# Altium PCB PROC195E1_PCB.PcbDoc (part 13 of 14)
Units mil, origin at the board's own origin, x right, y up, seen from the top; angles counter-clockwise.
Board outline 3110.24 x 2500 mil, 10 copper layers (Top Layer, L02_GND1, L03_SIG1, L04_GND2, L05_PWR1, L06_PWR2, L07_GND3, L08_SIG2, L09_GND4, Bottom Layer), stack 66.407 mil thick; 571 components, 538 nets, 6726 pads, 1286 vias.
Unrouted connection lines stored in the file: 4.
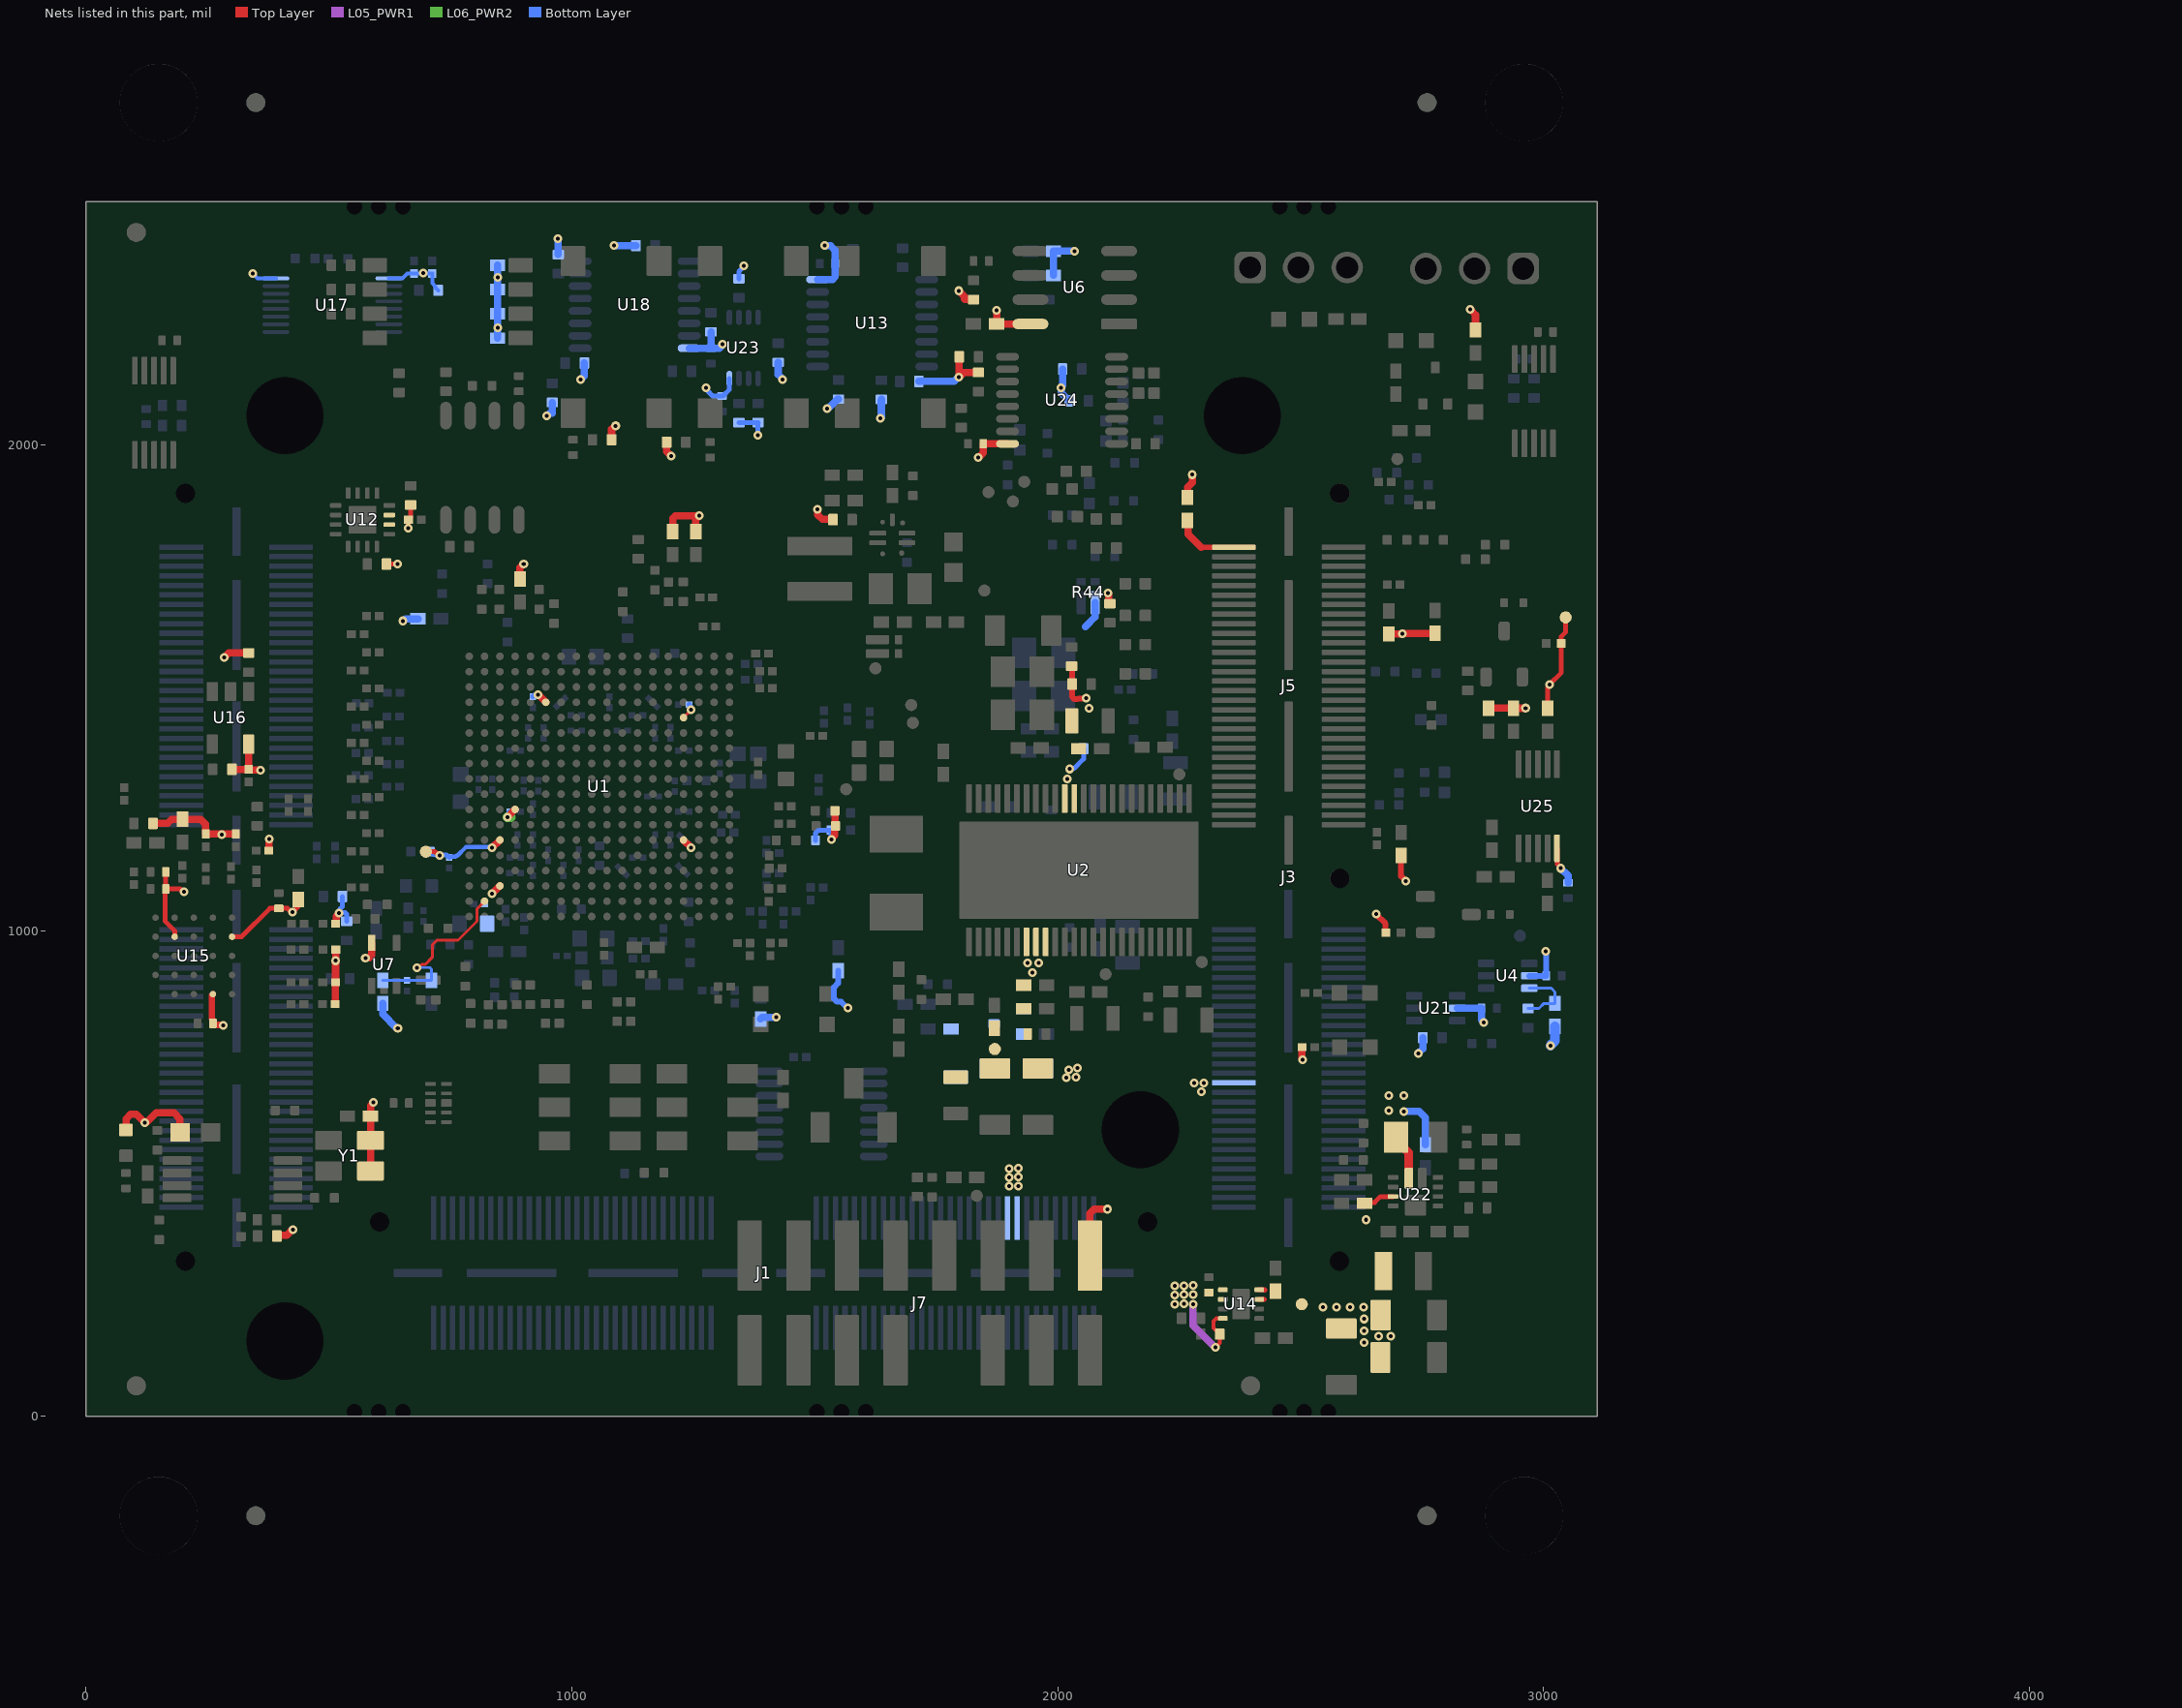
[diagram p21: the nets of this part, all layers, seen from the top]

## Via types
v1: diameter 18, hole 8, Top Layer to Bottom Layer, tented both sides, 1226 vias
v2: diameter 19.68, hole 7.87, Top Layer to Bottom Layer, tented top, 54 vias
v3: diameter 19.68, hole 7.87, Top Layer to Bottom Layer, 4 vias
v4: diameter 19.68, hole 7.87, Top Layer to Bottom Layer, tented both sides, 2 vias

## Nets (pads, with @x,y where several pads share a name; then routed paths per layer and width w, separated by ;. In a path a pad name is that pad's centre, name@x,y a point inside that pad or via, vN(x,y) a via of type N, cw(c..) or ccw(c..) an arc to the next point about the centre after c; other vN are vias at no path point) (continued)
VDDS18_LDO_1V8: C40.1 C44.1 C45.1 C46.1 C47.1 C48.1 U1.D6 U1.E15 U1.L4 U1.N15 U1.T3 U7.5 | length 210.6
  Top Layer w5.8: U1.E15@1230.11,1438.42 v1(1245.86,1454.17)
  Top Layer w15: v1(575.42,943.31) 575.99,943.89 583.25,943.89 588.39,949.02 U7.5@588.39,974.72 ; v1(836.41,1076.22) U1.T3@852.16,1091.97 ; v1(867.91,1233.7) U1.L4@883.65,1249.45 ; v1(930.9,1485.67) U1.D6@946.64,1469.92 ; U1.N15@1230.11,1186.45 v1(1245.86,1170.71)
  L06_PWR2 w20: v1(867.91,1233.7) 874.3,1233.7 v1@874.4,1233.8
  Bottom Layer w10: v1(867.91,1233.7) 867.91,1235.86 870.82,1238.78 870.82,1243.4 872.12,1244.7 C45.1@872.91,1244.7 ; C47.1@919.9,1481.22 919.9,1482 921.2,1483.3 921.98,1483.3 922.81,1484.14 929.37,1484.14 v1(930.9,1485.67) ; C44.1@1238.54,1179.19 1238.54,1178.61 1245.86,1171.29 v1(1245.86,1170.71) ; C48.1@1241.41,1465.17 1242.2,1465.17 1243.49,1463.87 1243.49,1463.08 1244.33,1462.25 1244.33,1455.7 v1(1245.86,1454.17)
VMAIN_5V0: C62.1 C80.1 C84.1 C85.1 C92.1 L3.1 R12.2 R58.1 R249.1 TP3.1 U14.7 U14.8 U22.9 | length 222
  Top Layer w10: U14.7@2414.76,241.02 2414.84,241.1 2425.74,241.1 ; U14.8@2414.76,260.71 2414.84,260.63 2426.27,260.63 2426.78,260.12 ; C92.1@2631.61,438.59 2633.6,440.57 2652.26,440.57 2664.3,452.61 U22.9@2690.19,452.61
  Top Layer w15: R58.1@2502.85,759.91 2502.85,736.24 2503.95,735.14 v1(2503.95,734.33)
  Bottom Layer w15: R12.2@611.15,850.21 611.28,850.09 611.28,828.11 639.63,799.76 641.58,799.76 v1(642.15,799.19)
  Bottom Layer w20: v1(3013.92,763.44) 3023.19,772.71 R249.1@3023.19,802.88
  other v1: 2630.86,151.86 2660.17,165.33 2685.15,165.35 2630.39,176.22 2630.27,200.57 2546.33,224.67 2574.01,224.67 2601.69,224.67 2629.37,224.67 2634.75,404.82
VMAIN_5V0_IN: C79.1 J1.18 J1.20 J3.27 R82.2 U14.1 U14.2 U14.4 | length 194
  Top Layer w8: v1(2324.25,141.98) 2333.58,151.31 R82.2@2333.58,169.51 2333.58,171.48 2327.74,177.32 2325.77,177.32 2321.02,182.08 2321.02,196 2326.91,201.89 2339.71,201.89 U14.4@2339.96,201.65
  L05_PWR1 w15: v1(2278.69,231.34) 2278.69,187.54 v1(2324.25,141.98)
  other v1: 2241.37,231.39 2260.04,231.77 2241.37,250.27 2260.04,250.46 2278.69,250.45 2241.37,269.15 2260.04,269.15 2278.69,269.55 1900.21,474.19 1919.42,474.49 1900.61,492.15 1918.97,493.16 1900.61,510.31 1918.77,510.91 2296.23,668.16 2280.72,686.14 2300.95,686.14
VMAIN_12V0: C58.1 C59.2 C60.2 C63.1 C64.1 C65.2 C66.2 C67.1 C68.1 C69.1 C94.1 C100.2 C167.1 C168.1 R16.2 R190.2 TP6.1 U2.7 U2.8 U2.9 U22.6 | length 201.5
  Top Layer w18: C100.2@2696.77,574.77 2696.77,568.27 2722.67,542.37 U22.6@2722.67,490.01
  Bottom Layer w15: v1(2712.11,627.97) 2743.98,627.97 2756.8,615.14 R190.2@2756.8,559.14
  other v1: 2681.85,629.37 2681.85,660.61 2712.11,660.61 2018.15,696.97 2037.81,698.38 2023.07,713.47 2040.62,717.33 1947.78,913.5 1938.54,933.46 1960.71,933.66
VMAIN_MON: R249.2 R251.1 U4.6 | length 139
  Bottom Layer w5.8: R251.1@2968,839.54 2990.11,839.54 3000.7,850.12 R249.2@3023.19,850.12 3023.19,873.79 3015.61,881.37 U4.6@2970.56,881.37
VPP_1V8: C23.1 R10.1 TP1.1 U1.N3 | length 203.3
  Top Layer w10: TP1.1@699.97,1162.37 700.03,1162.31 718.8,1162.31 720.46,1160.65 726.89,1154.23 v1(728.66,1154.23)
  Top Layer w15: v1(836.41,1170.71) U1.N3@852.16,1186.45
  Bottom Layer w9: R10.1@709.32,1162.37 709.32,1161.88 714.17,1157.03 714.66,1157.03 715.75,1155.95 v1@720.46,1155.95 ; C23.1@749.48,1152.31 760.79,1152.31 762.87,1154.38 765.04,1154.38 782.32,1171.67 v1@837.37,1171.67
  Bottom Layer w10: v1(728.66,1154.23) 727.13,1155.76 720.65,1155.76 720.46,1155.95 742.68,1155.95 745.81,1152.82 746.6,1152.82 747.89,1151.52 C23.1@747.89,1150.73
VREF_DEBUG: J5.1 R59.1 | length 133.7
  Top Layer w11: 2294.85,1789.15 J5.1@2362.59,1789.15
  Top Layer w15: R59.1@2267.59,1843.82 2268.06,1843.35 2268.06,1815.94 2294.85,1789.15
VSYS_3V3_LDO1: C56.1 C75.2 C76.1 C77.1 C78.1 C95.1 C104.1 C105.1 C129.1 C130.2 C131.1 C137.1 C138.1 C139.1 C140.1 C141.1 C156.1 C157.1 C160.1 C161.1 C174.1 FB3.1 J7.1 R19.1 R20.1 R21.1 R22.1 R37.2 R40.2 R41.1 R44.3 R46.2 R47.2 R48.2 R49.2 R50.2 R59.2 R68.1 R80.2 R81.2 R104.2 R105.2 R157.2 R158.2 R175.2 R176.2 R177.2 R178.2 R179.2 R180.2 R181.2 R182.2 R183.2 R184.1 R185.2 R202.2 R203.2 R205.2 R206.2 R216.1 R218.2 R219.2 R220.2 R221.2 R222.2 R233.2 R234.2 R245.1 R246.1 R248.1 R250.1 R252.1 R253.1 R254.1 R255.1 R256.1 R257.1 R260.2 R266.2 R267.2 R268.2 R279.2 R280.2 R298.1 R299.1 R300.1 R301.1 R304.1 R305.1 R306.1 R307.1 R308.1 TP10.1 U2.37 U2.38 U4.5 U6.8 U12.14 U12.15 U13.16 U15.B4 U15.D1 U15.E4 U16.5 U17.1 U17.16 U18.16 U21.5 U23.8 U24.16 U25.10 Y1.1 Y1.4 | length 4831.7
  Top Layer w10: C137.1@164.77,1120.78 C140.1@164.77,1085.78 ; U15.B4@182.96,987.35 182.89,987.42 182.89,999.65 163.81,1018.73 163.81,1084.82 C140.1@164.77,1085.78 ; v1(201.76,1079.47) 200.41,1079.47 194.1,1085.78 C140.1@164.77,1085.78 ; U15.E4@301.07,987.35 320.57,987.35 378.93,1045.71 415.33,1045.71 421.28,1039.76 421.96,1039.76 423.49,1038.23 v1(425.65,1038.23) 437.26,1049.83 C75.2@437.28,1064.05 ; R80.2@618.86,1754.31 619,1754.45 641.5,1754.45 v1(641.64,1754.59) ; v1(663.86,1828.23) 663.99,1828.36 663.99,1845.36 C131.1@664.12,1845.49 ; C131.1@664.9,1845.49 668.17,1848.76 668.17,1854.16 668.63,1854.62 R81.2@668.63,1876.03 ; R268.2@3008.15,1457.6 3008.15,1500.45 3012.01,1504.31 v1(3012.01,1506.48) 3036.51,1530.98 R280.2@3036.51,1591.21 3036.51,1605.47 3045.37,1614.33 TP10.1@3045.37,1644.52 ; U25.10@3027.57,1169.45 3028.48,1168.54 3028.48,1136.82 3034.86,1130.44 v1(3034.86,1128.28)
  Top Layer w12: R22.1@2028.96,1544.31 2029.4,1543.86 2029.4,1507.71 R21.1@2029.84,1507.27 2029.84,1481.07 2034.53,1476.38 2041.16,1476.38 2042.38,1477.6 2057.68,1477.6 v1(2058.82,1478.75) ; v1(2655.2,1033.91) 2674.77,1014.34 2674.77,996.11 R279.2@2675.24,995.64 ; R260.2@2706.82,1154.94 2706.82,1111.99 2716.57,1102.24 v1(2716.57,1101.82)
  Top Layer w13: C139.1@261.7,807.27 263.07,805.9 280,805.9 281.22,804.67 v1(282.57,804.67) ; C139.1@261.7,809.24 260.33,810.61 260.33,817.98 259.88,818.42 259.88,867.32 261.7,869.13 U15.D1@261.7,869.24
  Top Layer w15: FB3.1@82.8,589.68 82.8,612.3 92.28,621.78 104.39,621.78 v1(121.78,604.39) 122.59,604.39 124.09,605.89 125.89,605.89 144.66,624.66 181.83,624.66 194.19,612.3 C129.1@194.19,584.5 ; R183.2@138.5,1220.75 168.35,1220.75 176.88,1229.28 R180.2@199,1229.28 236.4,1229.28 246.98,1218.69 R179.2@246.98,1198.97 277.92,1198.97 279.31,1197.58 v1(280.12,1197.58) 280.93,1197.58 282.32,1198.97 R178.2@308.96,1198.97 ; v1(282.57,804.67) v1@283.15,804.1 ; v1(284.5,1562.09) 285.31,1562.09 294.52,1571.31 R205.2@335.2,1571.31 ; R206.2@300.75,1332.07 300.87,1331.95 335.08,1331.95 C141.1@335.2,1331.83 ; U16.5@335.2,1383.67 335.2,1331.19 335.96,1330.42 359.25,1330.42 v1(359.82,1329.85) ; R182.2@376.93,1164.69 377.55,1165.31 377.55,1188.42 v1(377.85,1188.72) ; R46.2@393.24,371.39 395.06,373.21 413.73,373.21 425.15,384.62 v1(425.96,384.62) ; R175.2@513.37,848.86 513.57,849.06 513.57,893.56 514.12,894.1 514.12,937.61 v1(514.46,937.95) ; v1@514.27,938.27 514.27,960.08 R176.2@514.41,960.22 ; R177.2@515.15,1014.32 515.57,1014.73 515.57,1029.72 521.4,1035.56 v1(521.4,1036.37) ; Y1.4@585.95,505.16 Y1.1@585.95,568.15 585.95,640.1 591.6,645.76 v1(591.6,646.57) ; R157.2@893.69,1723.67 893.69,1746.82 901.23,1754.36 v1(901.23,1754.65) ; R245.1@1082.1,2010.26 1082.1,2032.06 1088.48,2038.44 1089.98,2038.44 v1(1090.55,2039.01) ; R250.1@1195.53,2005.26 1195.53,1986.67 1205.02,1977.18 v1(1205.02,1977.12) ; R202.2@1207.93,1821.07 1207.93,1848.24 1213.49,1853.8 v1@1262.1,1853.8 ; R203.2@1255.29,1821.07 1255.29,1846.18 v1(1262.91,1853.8) ; v1(1505.31,1867.23) 1505.89,1866.66 1505.89,1856.03 1515.6,1846.32 R37.2@1537.68,1846.32 ; v1(1534.08,1187.61) 1534.08,1188.42 1541.32,1195.65 1541.32,1213.44 R104.2@1543.17,1215.29 ; R104.2@1541.81,1216.16 R105.2@1541.81,1246.63 ; v1(1796.85,2139.23) 1797.22,2139.61 1797.22,2180.75 R256.1@1797.52,2181.04 ; v1(1796.85,2317.03) 1796.85,2316.22 1807.58,2305.49 1807.58,2300.4 1809.09,2298.88 R252.1@1826.89,2298.88 ; v1@1798.23,2139.81 1807.31,2148.89 R257.1@1836.89,2148.89 ; v1(1836.26,1973.36) 1837.07,1973.36 1846.89,1983.17 C160.1@1846.89,2002.06 U24.16@1896.89,2002.06 ; v1(1874.74,2276.26) 1874.38,2275.89 1874.38,2248.98 C77.1@1874.01,2248.61 U6.8@1944.01,2248.61 ; J7.1@2066.47,331.06 2066.47,417.94 2075.26,426.73 v1(2102.75,426.73) ; v1(2103.36,1694.92) 2104.89,1693.39 2104.89,1675.65 R19.1@2107.45,1673.09 ; R59.2@2267.07,1891.58 2267.07,1912.79 2277.1,1922.81 v1@2277.1,1938.36 ; R216.1@2681.28,1610.44 2681.51,1610.67 2709.15,1610.67 2709.81,1611.32 2776.22,1611.32 R40.2@2776.65,1611.76 ; v1(2849.24,2278.26) 2859.8,2267.7 R68.1@2859.8,2236.18 ; R266.2@2886.74,1457.68 2886.79,1457.64 R267.2@2938.15,1457.6 R267.2@2938.15,1457.6 2962.48,1457.6 v1(2962.96,1458.07)
  Bottom Layer w8: v1(343.26,2352.54) 353.38,2342.42 U17.16@391.42,2342.42 ; U17.1@623.7,2342.42 651.26,2342.42 661.29,2352.45 C78.1@675.4,2352.45 675.8,2352.84 693.88,2352.84 v1(694.28,2353.24) 694.67,2352.84 712.67,2352.84 C76.1@713.06,2352.45 713.06,2332.07 719.25,2325.88 719.25,2323.79 R222.2@725.09,2317.95
  Bottom Layer w10: R185.2@528.27,1070.27 528.27,1049.46 523.18,1044.38 523.18,1043.81 522.93,1043.56 522.93,1037.9 v1(521.4,1036.37) 522.24,1037.21 533.66,1037.21 537.17,1033.69 R184.1@537.17,1019.27 ; v1(1275.99,2116.87) 1275.99,2114.71 1284.52,2106.18 1284.52,2106.08 1290.38,2100.22 C161.1@1309.22,2100.22 1311.19,2100.22 1324.48,2113.51 U23.8@1324.48,2136.43 ; R248.1@1344.16,2045.58 R41.1@1383.53,2045.58 1383.45,2045.49 1383.45,2019.29 v1(1383.36,2019.2) ; R253.1@1344.16,2341.78 1344.16,2356.82 1354.31,2366.97 v1(1354.31,2368.34) ; R234.2@1501.58,1185.59 1501.65,1185.65 1501.65,1200.33 1508.21,1206.89 R233.2@1533.7,1206.89 1533.89,1206.7 1533.89,1187.8 v1(1534.08,1187.61) ; v1(2024.59,1332.56) 2026.12,1334.09 2034.02,1334.09 2053.4,1353.47 R20.1@2053.4,1374.47
  Bottom Layer w12: R47.2@1548.35,917.56 1548.35,892.1 1539.61,883.36 1539.61,859.91 1546.03,853.49 1554.51,853.49 1567.61,840.4 v1(1568.29,840.4) ; U4.5@2970.56,906.96 C157.1@3005.56,906.96 3005.56,956.13 v1(3004.47,957.23)
  Bottom Layer w15: v1(652.78,1637.44) 653.59,1637.44 657.95,1641.8 R158.2@683.73,1641.8 ; R221.2@847.63,2219.54 v1(847.63,2241.19) R220.2@847.63,2269.54 R219.2@847.63,2319.54 v1(847.63,2344.54) R218.2@847.63,2369.54 ; v1(948.91,2059.78) 949.72,2059.78 954.72,2064.77 960.1,2064.77 R304.1@960.1,2087.12 ; v1(971.19,2423.85) 971.19,2423.04 972.3,2421.93 R306.1@972.3,2391.57 ; v1(1018.04,2133.93) 1026.01,2141.9 R305.1@1026.01,2168.12 ; v1(1087.54,2409.8) R307.1@1132.13,2409.8 ; U18.16@1241.71,2198.65 C56.1@1286.71,2198.65 ; R308.1@1286.71,2232.34 C56.1@1286.71,2198.65 ; v1(1310.32,2206.78) 1310.32,2205.96 1308.06,2203.7 1308.06,2202.83 1303.88,2198.65 1289.06,2198.65 C56.1@1286.71,2198.65 ; R48.2@1388.78,818.12 1391.95,821.29 1419.96,821.29 v1(1420.53,821.86) ; R301.1@1424.91,2169.57 1424.91,2144.25 1434.13,2135.03 v1(1434.13,2134.22) ; U13.16@1506.16,2340.02 1536.55,2340.02 1542.11,2345.59 1542.11,2399.9 1532.51,2409.5 1521.59,2409.5 v1(1521.01,2410.07) ; v1(1525.47,2074.06) 1526.05,2074.63 1527.67,2074.63 1546.92,2093.88 R300.1@1548.89,2093.88 ; v1(1635.04,2054.25) 1635.04,2055.06 1637.14,2057.17 1637.14,2091.01 1637.24,2091.1 R298.1@1637.24,2093.35 ; R299.1@1714.44,2130.44 1787.32,2130.44 1796.12,2139.23 v1(1796.85,2139.23) ; R49.2@1991.25,2348.61 R50.2@1991.25,2398.61 v1(2035.19,2398.61) ; R255.1@2010.22,2155.79 2010.22,2151.56 2010.13,2151.48 2010.13,2121.4 2006.92,2118.19 v1(2006.92,2117.38) 2007.5,2116.8 2007.5,2106.72 R254.1@2023.86,2090.36 ; 2056.94,1625.9 2076.99,1645.94 2076.99,1674.86 R44.3@2077.07,1674.95 ; v1(2741.86,746.66) 2741.86,747.47 2751.44,757.05 R246.1@2751.44,779.4 ; U21.5@2822.2,840.27 C156.1@2872.2,840.27 2872.2,816.42 2877.12,811.5 v1(2877.12,810.69) ; v1(3034.86,1128.28) 3050.22,1112.91 C174.1@3050.22,1098.29
  other v1: 2019.68,1311.78 2064.77,1457.57 2709.38,1610.89 2277.15,1938.41
VSYS_MON_AM26x: C57.1 R12.1 R13.2 U1.U2 | length 380.3
  Top Layer w5.66: 804.91,1018.93 804.91,1044.72
  Top Layer w5.8: v1(681.68,923.27) 683.75,923.27 691.18,930.69 698.81,930.69 713.11,944.99 713.11,970.58 722.68,980.15 766.14,980.15 773.33,987.34 778.16,992.17 804.91,1018.93 ; 804.91,1044.72 U1.U2@820.66,1060.47
  Bottom Layer w5.8: R12.1@611.15,897.46 C57.1@661.15,897.46 R13.2@711.15,897.46 711.15,920.66 707.75,924.06 682.47,924.06 v1(681.68,923.27)
pads on no net: Designator7. Designator7_1. Designator8. Designator8_1. Designator9. Designator9_1. FID1.1 FID2.1 FID3.1 FID4.1 FID5.1 FID6.1 FID7.1 FID8.1 FID9.1 FID10.1 FID12.1 FID13.1 FID14.1 FID15.1 J1.27 J1.40 J1.42 J1.44 J1.46 J1.47 J1.62 J1.64 J1.66 J1.68 J1.76 J1.79 J1.80 J1.81 J1.82 J1.84 J1.86 J1.88 J1.MH1 J1.MH2 J2.12 J2.24 J2.27 J2.29 J2.31 J2.33 J2.35 J2.37 J2.39 J2.41 J2.42 J2.43 J2.44 J2.45 J2.47 J2.49 J2.51 J2.61 J2.62 J2.63 J2.64 J2.65 J2.66 J2.67 J2.68 J2.69 J2.70 J2.71 J2.72 J2.73 J2.74 J2.75 J2.76 J2.77 J2.78 J2.79 J2.80 J2.81 J2.82 J2.83 J2.84 J2.85 J2.86 J2.87 J2.88 J2.89 J2.90 J2.91 J2.92 J2.93 J2.94 J2.95 J2.96 J2.97 J2.98 J2.99 J2.100 J2.101 J2.102 J2.103 J2.104 J2.105 J2.106 J2.107 J2.108 J2.109 J2.111 J2.MH1 J2.MH2 J3.1 J3.2 J3.3 J3.4 J3.5 J3.6 J3.7 J3.8 J3.9 J3.10 J3.11 J3.12 J3.13 J3.14 J3.15 J3.16 J3.17 J3.18 J3.19 J3.20 J3.21 J3.22 J3.23 J3.24 J3.25 J3.26 J3.28 J3.30 J3.32 J3.34 J3.36 J3.38 J3.39 J3.40 J3.41 J3.42 J3.43 J3.44 J3.45 J3.46 J3.47 J3.48 J3.49 J3.50 J3.51 J3.52 J3.53 J3.55 J3.58 J3.60 J3.61 J3.62 J3.63 J3.64 J3.65 J3.67 J3.69 J3.71 J3.73 J3.74 J3.75 J3.77 J3.79 J3.81 J3.86 J3.98 J3.103 J3.107 J3.110 J3.MH1 J3.MH2 J5. J5.8 J5.9 J5.10 J5.11 J5.14 J5.18 J5.20 J5.22 J5.24 J5.26 J5.28 J5.30 J5.32 J5.34 J5.36 J5.38 J5.40 J5.42 J5.44 J5.46 J5.48 J5.50 J5.51 J5.52 J5.53 J5.54 J5.55 J5.56 J5.59 J5.60 J8.2 J9.2 MH1.1 MH2.1 MH3.1 MH4.1 U7.1 U9.3 U10.3 U11.8 U11.9 U11.10 U12.17@569.55,1845.49 U13.13 U15.A2 U15.A3 U15.B1 U15.B5 U15.C5 U20.3@742.01,645.23 U20.4 U20.6 U20.7 U20.8@709.14,645.23 U22.0

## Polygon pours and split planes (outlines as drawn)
VSYS_3V3_LDO1 on L05_PWR1 "NONET_L08_P-001" (solid, remove dead copper, pour order 109): 0,2500 0,0 3110.24,0 3110.24,2500
VDDA_3V3 on L05_PWR1 "NONET_L08_P-001" (solid, remove dead copper, pour order 88): 1184.22,979.48 1190.02,973.68 1190.02,788.7 1284.52,694.2 1469.5,694.2 1499.57,664.12 1499.57,622.1 1466.37,588.9 795.53,588.9 780.23,573.6 678.67,573.6 651,601.28 651,661.55 688.63,699.18 740.93,699.18 756.64,714.9 816.6,714.9 910.85,714.9 1056.88,860.93 1055,972.34 1062.14,979.48
VMAIN_12V0 on L05_PWR1 "NONET_L08_P-001" (solid, remove dead copper, pour order 89): 2757.6,684.51 2679.96,762.15 2679.96,982.8 2670.51,992.24 1958.84,992.24 1920.28,953.69 1920.28,695.73 1955.8,660.21 2039.77,660.21 2113.24,733.68 2113.24,736.1 2356.99,736.1 2487.1,605.99 2728.79,605.99 2736.77,614.77 2757.6,635.6
VCC_1V2 on L05_PWR1 "NONET_L08_P-001" (solid, remove dead copper, pour order 86): 890.66,1155.07 898.11,1147.63 1093.07,1147.63 1120.5,1120.2 1437.73,1120.2 1610.67,1293.14 1610.67,1578.88 1597.25,1592.29 1413.83,1592.29 1321.85,1684.28 794.18,1684.28 706.44,1596.55 706.44,1267.24 878.82,1267.24 890.66,1255.39
DAC_VREF on L05_PWR1 "NONET_L-01_P-001" (solid, remove dead copper, pour order 80): 1181.69,1093.43 1559.34,1093.43 1575.41,1077.36 1575.41,1000.43 1556.98,982 1210.37,982 1170.37,1022 1170,1022 1170,1081.74
VDDA18_OSC_PLL_AM26x on L05_PWR1 "NONET_L08_P-001" (solid, remove dead copper, pour order 92): 867.9,1183.71 688.67,1183.71 678.22,1173.26 678.22,1078.76 687.4,1069.59 865.31,1069.59 881.56,1085.84 881.56,1171.32 874.38,1178.51
VDDA18_LDO_1V8 on L05_PWR1 "NONET_L08_P-001" (solid, remove dead copper, pour order 81): 999.93,1119.73 991.47,1128.19 913.6,1128.19 913.6,1069.29 1000.39,1069.29 1006.19,1075.09 1006.19,1115.18
GND on Bottom Layer "GND_L10_P103" (solid, remove dead copper, pour order 103): 0,2500 3110.24,2500 3110.24,0 0,0
VDD_IO_3V3 on Bottom Layer "NONET_L08_P-001" (solid, remove dead copper, pour order 0): 2044.88,1698.21 2034.02,1709.07 2023.26,1709.07 2019.05,1704.87 2019.05,1651.45 2026.34,1644.16 2036,1644.16 2042.81,1650.97 2060.59,1650.97 2061.74,1652.12 2061.74,1697.04 2060.57,1698.21
GND on Bottom Layer "NONET_L08_P-001" (solid, remove dead copper, pour order 52): 2036.46,1603.56 2019.08,1620.95 2019.08,1719.76 2017.11,1721.34 1947.41,1721.34 1947.41,1670.79 1971.46,1646.74 1971.46,1356.07 2012.8,1356.07 2016.84,1360.11 2016.84,1424.44 2036.46,1443.49
VMAIN_12V0 on Bottom Layer "NONET_L08_P-001" (solid, remove dead copper, pour order 33): 1926.45,935.67 1926.45,931.21 1899.58,904.16 1899.58,830.11 1888.81,819.34 1771.78,819.34 1757.31,804.87 1757.31,679.88 1766.14,671.05 2055.32,671.05 2070.48,686.21 2070.48,740.07 2055.42,755.13 1958.19,755.13 1945.42,767.91 1945.42,886.13 1965.1,905.82 1965.1,924.32 1965.1,939.77 1962.05,942.82 1933.6,942.82
VDD_IO_3V3 on Bottom Layer "NONET_L08_P-001" (solid, remove dead copper, pour order 7): 1550.42,1403.93 1550.42,1300.28 1603.34,1300.28 1612.9,1309.85 1612.9,1394.36 1603.34,1403.93
VCC_1V2 on Bottom Layer "NONET_L08_P-001" (solid, remove dead copper, pour order 38): 753.84,1305.09 748.91,1310.02 735.27,1310.02 725.48,1319.81 725.48,1339.58 731.85,1345.95 840.43,1345.95 847.94,1338.44 847.94,1330.93 862.96,1315.92 884.18,1294.69 937.14,1294.69 942.89,1288.94 942.89,1258.57 937.97,1253.66 913.6,1253.66 910.86,1256.4 892.27,1256.4 885.18,1263.49 885.18,1271.81 873.78,1283.2 851.89,1305.09 834.83,1305.09
VCC_1V2 on Bottom Layer "NONET_L08_P-001" (solid, remove dead copper, pour order 1): 1080.76,1655.54 1091.87,1644.43 1091.87,1613.46 1072.51,1594.11 1072.51,1514.34 1082.82,1504.04 1098.52,1504.04 1105.55,1497.01 1105.55,1478.36 1097.38,1470.19 1071.19,1470.19 1064.04,1463.04 1064.04,1417.86 1051.55,1405.38 1013.3,1405.38 1013.3,1462.84 1018.22,1467.76 1032.71,1467.76 1039.28,1474.32 1039.28,1528.29 1032.79,1534.78 1032.79,1646.41 1041.92,1655.54
VCC_6V0 on Bottom Layer "NONET_L08_P-001" (solid, remove dead copper, pour order 48): 1837.54,1514.63 1820,1532.17 1820,1643 1837.54,1660 1837.54,1749.84 1796.26,1791.13 1796.26,1817.53 1831.75,1853.02 1855.95,1853.02 1905.97,1803.01 1920.94,1788.03 1920.94,1655.42 1955.71,1620.65 1955.71,1615.57 1955.71,1346.14 1961.51,1340.34 1961.51,1304.13 1900.35,1304.13 1900.35,1351.67 1896.06,1355.96 1853.71,1355.96 1837.54,1372.13
VDDA_3V3 on Bottom Layer "NONET_L08_P-001" (solid, remove dead copper, pour order 62): 1062.67,1008.75 1089.49,1008.75 1090.64,1007.6 1090.64,993.63 1105.23,979.05 1105.23,935.37 1061.4,935.37 1060.28,936.49 1060.28,1007.16 1061.29,1008.18
GND on Bottom Layer "NONET_L08_P-001" (solid, remove dead copper, pour order 5): 1428.35,1396.14 1431.6,1392.9 1431.6,1353.33 1427.6,1349.33 1330.2,1349.33 1318.92,1338.05 1298.66,1338.05 1294.85,1341.87 1294.85,1368.72 1300.71,1374.59 1316.19,1374.59 1337.75,1396.14
VSYS_3V3_LDO1 on Bottom Layer "NONET_L08_P-001" (solid, remove dead copper, pour order 61): 2089.17,1700.86 2093.02,1704.71 2113.37,1704.71 2114.43,1703.64 2114.43,1691.45 2114.43,1649.35 2079.79,1614.71 2079.79,1484.04 2079.79,1446.04 2079.79,1401.21 2064.92,1386.34 2064.92,1353.86 2037.05,1325.99 2037.05,1310.81 2024.98,1298.74 2012.92,1298.74 2006.82,1304.84 2006.82,1328.71 2032.24,1354.13 2032.24,1416.55 2051.91,1436.21 2051.91,1635.51 2068.3,1651.9 2067.68,1652.52 2067.68,1695.21 2073.33,1700.86
GND on Bottom Layer "NONET_L08_P-001" (solid, remove dead copper, pour order 39): 752.46,1277.05 720.73,1277.05 720.73,1230.85 722.19,1229.39 815.05,1229.39 821.95,1236.29 821.95,1269.8 835.19,1283.04 842.95,1283.04 842.95,1297.22 772.63,1297.22
VMAIN_5V0_IN on Bottom Layer "NONET_L08_P-001" (solid, remove dead copper, pour order 16): 1891.57,363.19 1891.57,464.1 1886.98,468.68 1886.98,512.62 1893.54,519.18 1923.12,519.18 1927.85,514.45 1927.85,469.41 1922.25,463.82 1922.25,363.19
GND on Bottom Layer "NONET_L08_P-001" (solid, remove dead copper, pour order 37): 1992.29,577.16 1774.34,577.16 1764.06,586.88 1764.06,643.03 1988.79,643.03 1992.29,639.54
VCC_1V2 on Bottom Layer "NONET_L08_P-001" (solid, remove dead copper, pour order 3): 1436.03,1283.01 1436.03,1334.12 1289.89,1334.12 1286.01,1338 1267.18,1338 1263.9,1334.72 1263.9,1311.71 1249.26,1297.07 1176.34,1297.07 1168.87,1289.6 1168.87,1263 1175.15,1256.73 1222.66,1256.73 1244.97,1279.04 1432.06,1279.04
GND on Bottom Layer "NONET_L08_P-001" (solid, remove dead copper, pour order 64): 949.57,933.53 945.04,933.53 941.63,936.74 941.63,992.44 947.55,992.44 963.85,1008.75 1032.81,1008.75 1033.38,1008.18 1033.38,1007.37 1033.95,1006.8 1033.95,978.01 987.5,978.01 975.88,966.38 975.88,941.48 957.52,941.48
3V3_LDO2 on Bottom Layer "3V3_LDO2_L10_P096" (solid, pour order 96): 1834.58,560.18 1841.61,553.16 1841.61,517.8 1827.37,503.57 1827.37,456.73 1823.83,453.19 1823.83,363.19 1812.83,363.19 1812.83,453.19 1808.4,457.62 1808.4,555.07 1813.51,560.18
GND on Bottom Layer "NONET_L08_P-001" (solid, remove dead copper, pour order 8): 1688.66,1394.74 1688.66,1311.34 1677.6,1300.28 1635.74,1300.28 1626.18,1309.85 1626.18,1394.36 1635.74,1403.93 1679.59,1403.93
GND on Bottom Layer "NONET_L08_P-001" (solid, remove dead copper, pour order 2): 967.24,1645.47 983.27,1661.5 1002.55,1661.5 1017.19,1646.86 1017.19,1542.55 1017.79,1541.96 1013.81,1537.98 988.37,1537.98 983.18,1543.17 983.18,1585.38 967.24,1601.32
GND on Bottom Layer "NONET_L08_P-001" (solid, remove dead copper, pour order 97): 2751.83,256.37 2760.65,265.19 2904.54,265.19 2921.47,248.26 2921.47,132.5 2908.23,119.26 2762.82,119.26 2747.85,134.23 2747.85,250.69
GND on Bottom Layer "NONET_L08_P-001" (solid, remove dead copper, pour order 69): 701.26,1026.44 680.97,1026.44 673.2,1018.67 653.51,1018.67 653.51,995.04 700.35,995.04 701.26,995.95 701.26,1012.26
VDDS18_LDO_1V8 on Bottom Layer "NONET_L08_P-001" (solid, remove dead copper, pour order 47): 841.12,991.32 846.07,996.27 846.07,1083 841.8,1087.34 823.28,1087.34 822.23,1086.42 822.23,1070.66 812.04,1060.47 812.04,996.28 817.01,991.32
GND on Bottom Layer "NONET_L08_P-001" (solid, remove dead copper, pour order 72): 814.09,1086.39 769.39,1086.39 751.51,1068.51 751.51,998.6 759.72,990.39 789.32,990.39 794.16,995.23 794.16,1036.73 805.66,1048.23 805.66,1063.74 814.68,1072.76 814.68,1085.07
VDDA18_LDO_1V8 on Bottom Layer "NONET_L08_P-001" (solid, remove dead copper, pour order 68): 651.94,1180.89 676.93,1180.89 681.05,1176.77 681.05,1152.83 678.86,1150.64 678.86,1102.53 678.86,1070.82 678.86,1058.91 683.12,1054.65 695.61,1054.65 701.26,1049 701.26,1034.31 674.64,1034.31 674.54,1034.41 653.51,1034.41 641.71,1046.22 641.71,1170.66
VDD_IO_3V3 on Bottom Layer "NONET_L08_P-001" (solid, remove dead copper, pour order 65): 983.04,925.41 983.04,892.26 989.33,886.02 1034.97,886.02 1036.11,887.16 1036.11,955.96 1029.13,962.94 991.04,962.94 991.04,933.41
GND on Bottom Layer "NONET_L08_P-001" (solid, remove dead copper, pour order 63): 1057.37,915.24 1061.62,919.49 1091.65,919.49 1094.01,917.13 1094.01,870.71 1086.96,863.66 1068.64,863.66 1057.37,874.93
5V0_LDO3 on Bottom Layer "NONET_L08_P-001" (solid, remove dead copper, pour order 60): 2169.2,918.23 2172.84,921.87 2172.84,970.47 2165.17,978.14 2075.47,978.14 2075.47,932.13 2089.36,918.23
GND on Bottom Layer "NONET_L08_P-001" (solid, remove dead copper, pour order 36): 2005.84,873.59 1965.95,873.59 1961.17,868.81 1961.17,775.48 2007.06,775.48 2010.76,779.17 2010.76,868.68
GND on Bottom Layer "NONET_L08_P-001" (solid, remove dead copper, pour order 35): 1851.05,874.7 1851.05,883.88 1855.94,888.76 1882.52,888.76 1885.07,886.21 1885.07,876.33 1885.07,841.64 1879.93,836.49 1857.12,836.49 1851.05,842.55
VMAIN_12V0 on Bottom Layer "NONET_L08_P-001" (solid, remove dead copper, pour order 31): 2674.78,666.7 2670.1,662.03 2670.1,610.44 2674.42,606.12 2737.44,606.12 2740.52,609.21 2740.52,662.08 2735.9,666.7
VMAIN_5V0 on Bottom Layer "NONET_L08_P-001" (solid, remove dead copper, pour order 28): 2701.95,265.19 2712,255.14 2712,131 2700.26,119.26 2516.5,119.26 2503.26,132.5 2503.26,248.26 2520.19,265.19
VMAIN_5V0_IN on Bottom Layer "NONET_L08_P-001" (solid, remove dead copper, pour order 17): 2297.2,286.01 2207.11,286.01 2196.64,275.55 2196.64,196.88 2203.44,190.08 2314.63,190.08 2322.03,197.48 2322.03,281.63 2317.41,286.26
VMAIN_5V0_IN on Bottom Layer "NONET_L08_P-001" (solid, remove dead copper, pour order 9): 2290.49,658.61 2285.6,663.49 2285.6,668.31 2267.38,686.54 2267.38,691.86 2273.87,698.36 2303.07,698.36 2309.26,692.17 2407.59,692.17 2407.59,681.17 2310.15,681.17 2307.71,678.74 2307.71,665.99 2300.33,658.61
GND on L06_PWR2 "NONET_L08_P-001" (solid, remove dead copper, pour order 111): 0,2500 0,0 3110.24,0 3110.24,2500
VMAIN_5V0 on L06_PWR2 "NONET_L08_P-001" (solid, remove dead copper, pour order 78): 1880.27,227.73 1906.95,201.05 2410,201 2487.1,278.1 2487.1,746.02 2500.6,759.52 2953.69,759.52 2981.86,787.69 3089.23,787.69 3089.23,50.83 1580.29,50.83 1517.37,113.76 686.51,113.76 612.28,187.99 448.1,352.17 448.1,801.7 464.69,818.29 656.64,818.29 660.36,814.57 660.36,775.83 563.11,678.58 563.11,381.84 717.22,227.73
VDDA18_LDO_1V8 on L06_PWR2 "NONET_L08_P-001" (solid, remove dead copper, pour order 108): 1025,736.8 981.2,693 746,693 715.55,723.45 715.55,883.86 590.93,1008.48 590.93,1027.5 641.05,1077.62 680.54,1077.62 758.71,999.45 878.18,999.45 974.26,1095.53 974.26,1105.31 986.28,1117.33 1005.38,1117.33 1005.38,1113.44 1020.52,1098.3 1095.64,1098.3 1105.15,1107.82 1127.85,1107.82 1132.78,1102.89 1132.78,1057.82 1132.87,1057.72 1115.76,1040.61 1071.51,1040.61 970.4,939.51 827.51,939.51 819.46,931.45 819.46,864.28 862.34,821.4 890.55,793.19 1170.43,793.19 1198.64,821.4 1490.58,821.4 1498.65,813.33 1498.65,744.26 1491.18,736.8 1471.04,736.8 1454.24,720 1152.8,720 1136,736.8
3V3_LDO2 on L06_PWR2 "NONET_L08_P-001" (solid, remove dead copper, pour order 74): 2935,782.65 2985.74,782.65 3110.24,907.15 3110.24,2334.44 2944.68,2500 121.25,2500 67.56,2446.32 67.56,2237.09 114.36,2190.29 237.73,2190.29 281.68,2234.25 514.24,2234.25 607.83,2140.66 676.89,2140.66 765.09,2052.46 765.09,1785 787.33,1762.76 827.72,1762.76 898.27,1833.31 1806.34,1833.31 2197.02,2224 2477,2224 2645,2056 2728,2056 2778.05,2005.95 2778.05,1632.98 2715.2,1570.12 2715.2,1119.18 2576.03,980.01 2576.03,900.28 2540.62,864.87 2375.39,864.87 2344.74,896.28 1794.32,896.28 1722.25,824.21 1722.25,602.29 1784.61,539.93 1784.61,520.05 1834.79,520.05 1834.79,555.72 1813.61,576.9 1813.61,716.14 1852.1,754.63 2081.12,754.63 2113.75,722 2442.19,722 2474.82,754.63 2480.62,754.63 2508.64,782.65
VDD_IO_3V3 on L06_PWR2 "NONET_L08_P-001" (solid, remove dead copper, pour order 73): 1995.44,1443.68 2045,1493.24 2045,1721.69 2042.27,1724.42 1952.69,1814 911.87,1814 733.05,1635.18 733.05,1188.15 790.67,1130.53 877.5,1130.53 883.53,1135.71 883.53,1207.46 879.22,1211.78 848.36,1211.78 848.36,1272.29 865.57,1289.5 886.09,1289.5 915.75,1319.16 916.59,1319.16 916.59,1405.49 867.91,1454.17 867.91,1496.49 902.35,1530.94 948.62,1530.94 974.71,1504.84 974.71,1473.4 993.94,1454.17 1171.41,1454.17 1205.83,1488.6 1290.53,1488.6 1298.62,1480.51 1298.62,1430.09 1214.36,1345.84 1214.36,1233.7 1225.01,1223.05 1298.2,1223.05 1303.09,1218.16 1303.09,1158.9 1287.17,1142.97 1249.62,1142.97 1233.95,1127.31 1233.95,1011.34 1161.02,938.4 994.2,938.4 978.91,923.11 978.91,857.33 994.68,841.56 1165.11,841.56 1210.83,887.28 1303.73,887.28 1330.39,913.94 1482.78,913.94 1595,1026.16 1595,1321.42 1717.26,1443.68
VSYS_3V3_LDO1 on L06_PWR2 "NONET_L-01_P-001" (solid, pour order 18): 2188,1728 2092,1728 2065.39,1701.39 2065.39,1502.81 1997,1434.41 1997,1316.08 2023.08,1290 2094.24,1290 2145,1340.76 2145,1438 2224,1517 2224,1700
VDDS18_LDO_1V8 on L06_PWR2 "NONET_L08_P-001" (solid, remove dead copper, pour order 84): 592.29,1097.05 568.52,1073.27 568.52,973.22 592.29,949.45 592.29,896.6 581.56,885.87 415.85,885.87 406.65,895.07 406.65,1091.36 524.72,1212.89 675.1,1212.89 795.57,1092.42 855.39,1092.42 888.36,1125.39 888.36,1181.75 849.78,1220.33 848.1,1220.33 848.1,1245.39 867.91,1265.2 879.19,1265.19 930.9,1316.9 930.9,1427.01 899.4,1458.51 899.4,1517.16 930.9,1517.16 931.63,1517.89 961.66,1517.89 961.66,1486.4 962.39,1485.67 962.39,1452.54 975.86,1439.07 1142.22,1439.07 1188.81,1485.67 1244.79,1485.67 1260.7,1469.76 1260.7,1399.84 1249.96,1389.1 1234.12,1389.1 1203.67,1358.65 1203.67,1212.89 1214.36,1202.2 1256.68,1202.2 1256.68,1156.9 1196.79,1156.9 1121.25,1232.44 992.63,1232.44 944.66,1184.47 944.66,1091.99 870.33,1017.66 764.25,1017.66 684.86,1097.05
VMAIN_5V0_IN on L06_PWR2 "NONET_L08_P-001" (solid, remove dead copper, pour order 77): 2050.22,524.42 2118.48,456.16 2234.16,456.16 2309,531 2309,630.31 2279.65,659.66 2279.65,671.97 2270.23,681.39 2270.47,681.63 2270.47,700.06 2419.49,700.06 2459.13,660.42 2459.13,273.13 2406,220 1895,220 1850.08,264.92 1850.08,496.32 1878.19,524.42
VCC_6V0 on L06_PWR2 "NONET_L08_P-001" (solid, remove dead copper, pour order 82): 1962,1414.04 1965.7,1410.34 1965.7,1284.02 1962,1280.32 1834.04,1280.32 1830.34,1284.02 1830.34,1410.34 1834.04,1414.04
5V0_LDO3 on L06_PWR2 "NONET_L08_P-001" (solid, remove dead copper, pour order 83): 2528.29,879.75 2387.02,879.75 2353.52,913.25 2122.2,913.25 1785.51,913.25 1697.07,824.82 1697.07,597.98 1767.7,527.36 1767.7,492.35 1751.76,476.4 1679.82,476.4 1628.63,527.6 1628.63,891.69 1735.61,998.68 2534.71,998.68 2553,980.39 2553,914.93
VDDA_3V3 on L06_PWR2 "NONET_L08_P-001" (solid, remove dead copper, pour order 85): 1134.06,1119.82 1142.65,1111.23 1158.73,1095.15 1158.73,1049.5 1140.95,1031.72 1085.37,1031.72 1052.81,999.16 1052.81,973.68 1070.18,956.31 1134,956.31 1214.36,1036.67 1214.36,1127.67 1131.01,1211.01 988.64,1211.01 953.33,1175.7 953.33,1133.06 959.08,1127.31 1015.03,1127.31 1022.52,1119.82
GND on Top Layer "GND_L01_P110" (solid, remove dead copper, pour order 110): 0,2500 3110.24,2500 3110.24,0 0,0
GND on Top Layer "NONET_L08_P-001" (solid, remove dead copper, pour order 76): 2075.09,1426.39 2090.32,1441.62 2090.32,1474.5 2098.51,1483.21 2117.71,1483.21 2129.23,1471.69 2129.23,1415.32 2106.32,1392.41 2106.32,1362.66 2075.09,1362.66
VCC_6V0 on Top Layer "NONET_L08_P-001" (solid, remove dead copper, pour order 46): 1720.89,1812.28 1672.8,1812.28 1669.23,1815.85 1669.23,1823.92 1672.27,1826.96 1719.75,1826.96 1745.81,1853.02 1855.95,1853.02 1916.82,1792.15 1916.82,1414.02 1934.8,1396.04 1934.8,1367.24 1961.34,1340.7 1961.34,1243.56 1960.2,1242.42 1930.98,1242.42 1929.84,1243.56 1929.84,1322.18 1894,1358.02 1840.4,1358.02 1825.26,1373.16 1825.26,1762.05 1808.31,1779 1754.16,1779
VCC_1V2 on Top Layer "NONET_L08_P-001" (solid, remove dead copper, pour order 45): 1537.02,1579.66 1526.09,1568.74 1525.91,1568.74 1525.91,1493.09 1537.02,1482.62 1647.06,1482.62 1653.6,1489.16 1653.6,1579.66
+1V2 on Top Layer "NONET_L08_P-001" (solid, remove dead copper, pour order 42): 1589.34,1744.74 1603.48,1758.89 1603.48,1778.82 1608.21,1783.55 1648,1783.55 1652.7,1778.85 1652.7,1589.69 1495.56,1589.69 1491.67,1593.58 1491.67,1635.61 1470.05,1657.23 1440.98,1657.23 1440.98,1744.74
VSYS_3V3_LDO1 on Top Layer "NONET_L-01_P-001" (solid, remove dead copper, pour order 6): 643.32,1860.06 614.02,1860.06 612.86,1858.9 612.86,1832.09 614.02,1830.93 635.31,1830.93 638.24,1828 650.43,1828 659.54,1818.89 668.75,1818.89 668.75,1819.16 673.76,1824.17 673.76,1860.73 680.44,1867.41 680.44,1884.72 679.29,1885.87 657.97,1885.87 656.82,1884.72 656.82,1873.56
VCC_1V2 on Top Layer "NONET_L08_P-001" (solid, remove dead copper, pour order 95): 1409.37,1333.8 1401.98,1326.41 1401.98,1300.79 1408.01,1294.75 1463.54,1294.75 1468.05,1299.27 1468.05,1328.84 1465.12,1333.8
VMAIN_12V0 on Top Layer "Top Layer-VMAIN_12V0" (solid, remove dead copper, pour order 90): 2671.77,611.67 2671.77,523.8 2680.46,515.12 2705.64,515.12 2713.81,506.94 2713.81,469.86 2715.58,468.09 2730.08,468.09 2731.52,469.54 2731.52,667.89 2709.85,689.56 2487.64,689.56 2395.45,781.76 2095.16,781.76 2069.6,756.2 1968.23,756.2 1946,778.43 1946,901.53 1981.02,936.55 1981.02,948.29 1981.02,1005.06 1979.88,1006.2 1930.98,1006.2 1929.84,1005.06 1929.84,944.11 1926.33,940.59 1926.33,931 1899.58,904.25 1899.58,822.41 1892.33,815.16 1775,815.16 1757.31,797.47 1757.31,679.88 1766.14,671.05 2067.53,671.05 2115.16,718.68 2332.16,718.68 2421.72,629.12 2654.31,629.12
VDD_IO_3V3 on Top Layer "NONET_L08_P-001" (solid, remove dead copper, pour order 11): 1554.09,1301.29 1550.42,1304.96 1550.42,1348.02 1550.42,1394.74 1559.6,1403.93 1603.34,1403.93 1612.9,1394.36 1612.9,1310.81 1603.39,1301.29
NetC71_1 on Top Layer "NONET_L08_P-001" (solid, remove dead copper, pour order 50): 1791.33,1334.22 1784.56,1340.99 1715.39,1340.99 1706.35,1331.96 1706.35,1307.56 1679.06,1280.26 1592.42,1280.26 1586.65,1274.5 1586.65,1172.74 1598.64,1160.74 1770.98,1160.74 1787.67,1177.43 1787.67,1289.46 1808.62,1310.42 1841.41,1310.42 1851.1,1300.72 1851.1,1243.56 1852.24,1242.42 1881.46,1242.42 1882.6,1243.56 1882.6,1306.13 1854.51,1334.22
VSYS_3V3_LDO1 on Top Layer "NONET_L08_P-001" (solid, remove dead copper, pour order 75): 2061.05,1353.13 2061.05,1438.24 2072.43,1449.62 2072.43,1481.01 2066.32,1487.12 2028.65,1487.12 2016.59,1475.06 2016.59,1455.21 2016.15,1454.77 2016.15,1356.19 2008.02,1348.06 2008.02,1244.13 2009.73,1242.42 2038.94,1242.42 2040.08,1243.56 2040.08,1332.15
GND on Top Layer "NONET_L08_P-001" (solid, remove dead copper, pour order 57): 1995.07,579.96 1994.47,579.35 1750.99,579.35 1743.47,586.88 1743.47,628.62 1757.88,643.03 1984.79,643.03 1995.07,632.75
NetL1_1 on Top Layer "NONET_L08_P-001" (solid, remove dead copper, pour order 56): 1851.1,1004.25 1851.1,943.77 1846.48,939.14 1805.06,939.14 1775.22,968.99 1775.22,1105.64 1762.63,1118.22 1592.65,1118.22 1575.97,1101.55 1575.97,926.7 1597.9,904.77 1696.28,904.77 1711.64,889.41 1794.9,889.41 1812.62,907.13 1847.83,907.13 1882.45,941.76 1882.45,948.94 1882.6,949.09 1882.6,1005.06 1881.46,1006.2 1852.24,1006.2 1851.1,1005.06
GND on Top Layer "NONET_L08_P-001" (solid, remove dead copper, pour order 91): 1408.73,1390.91 1399.75,1381.92 1399.75,1355.97 1407.7,1348.02 1460.38,1348.02 1466.93,1354.57 1466.93,1383.23 1459.48,1390.91
3V3_LDO2 on Top Layer "NONET_L08_P-001" (solid, remove dead copper, pour order 53): 2023.68,894.05 2031.85,902.22 2046.61,902.22 2055.18,893.65 2055.18,846.24 2073.97,827.45 2073.97,779.14 2067.74,772.91 2032.96,772.91 2023.68,782.19
VMAIN_5V0_IN on Top Layer "NONET_L08_P-001" (solid, remove dead copper, pour order 59): 1896.06,520.43 1888.76,513.13 1888.76,465.36 1893,461.52 1926.32,461.52 1935,470.2 1935,517.8 1932.37,520.43
NetL2_1 on Top Layer "NONET_L08_P-001" (solid, remove dead copper, pour order 44): 1591.97,1768.01 1591.97,1785.65 1599.71,1793.39 1645.85,1793.39 1647.93,1795.48 1647.93,1801.61 1646.38,1803.16 1645.05,1803.24 1606.92,1803.24 1595.68,1814.48 1439.37,1814.48 1439.37,1755.64 1579.61,1755.64
GND on Top Layer "NONET_L08_P-001" (solid, remove dead copper, pour order 21): 2909.59,484.11 2920.84,495.36 2920.84,591.71 2910.89,601.66 2872.08,601.66 2853.52,583.1 2822.67,583.1 2801.77,562.21 2801.77,534.34 2778.52,511.1 2761.08,511.1 2759.08,509.1 2759.08,469.86 2757.58,468.36 2742.87,468.36 2741.37,469.86 2741.37,517.24 2751.77,527.64 2751.77,695.8 2768.41,712.44 2982.56,712.44 3044.92,650.07 3044.92,123.34 2984.54,62.96 2752.52,62.96 2738.96,76.53 2738.96,232.78 2746.89,240.71 2906.14,240.71 2925.52,260.09 2925.52,350.91 2872.17,404.26 2872.17,441.56 2872.17,484.11
GND on Top Layer "NONET_L08_P-001" (solid, remove dead copper, pour order 51): 2010.83,1471.12 2001.3,1461.58 2001.3,1376.09 1991.89,1366.67 1956.94,1366.67 1950.53,1373.09 1950.53,1403.82 1931.82,1422.53 1931.82,1729.08 1937.89,1735.15 2011.16,1735.15
3V3_LDO2 on Top Layer "3V3_LDO2_L01_P099" (solid, pour order 99): 1821.3,556.22 1815.08,550 1815.08,506.65 1817.97,503.76 1817.97,480.13 1849.46,480.13 1849.46,556.22
GND on Top Layer "NONET_L08_P-001" (solid, remove dead copper, pour order 79): 681.05,1853.76 699.16,1853.76 699.16,1823.95 696.79,1821.59 685.59,1821.59 681.05,1826.13 681.05,1837.23
5V0_LDO3 on Top Layer "NONET_L08_P-001" (solid, remove dead copper, pour order 55): 2087.32,1004.25 2087.32,945.23 2079.8,937.71 2079.8,922.05 2084.65,917.21 2084.65,901.58 2090.02,896.21 2108.4,896.21 2112.94,900.76 2112.94,919.55 2099.13,933.36 2099.13,1004.25 2098.56,1004.82 2098.56,1005.63 2097.76,1005.63 2097.19,1006.2 2088.47,1006.2 2087.89,1005.63
GND on Top Layer "NONET_L08_P-001" (solid, remove dead copper, pour order 54): 2102.58,885.36 2071.08,885.36 2071.08,861.74 2088.64,844.18 2088.64,793.47 2137.93,793.47 2137.93,851.46 2120.97,868.43
GND on Top Layer "NONET_L08_P-001" (solid, remove dead copper, pour order 49): 1768.36,1623.54 1768.5,1623.4 1809.31,1623.4 1811.18,1625.17 1811.18,1738.96 1794.76,1755.38 1714.62,1755.38 1707.06,1762.95 1707.06,1782.5 1706,1783.55 1672.53,1783.55 1665.6,1776.62 1665.6,1679.93 1679.9,1665.63 1760.39,1665.63 1768.36,1657.66
GND on Top Layer "NONET_L08_P-001" (solid, remove dead copper, pour order 13): 1688.66,1394.74 1688.66,1311.34 1677.6,1300.28 1635.74,1300.28 1633.5,1302.53 1633.5,1401.69 1635.74,1403.93 1679.59,1403.93
GND on Top Layer "NONET_L08_P-001" (solid, remove dead copper, pour order 41): 1857.08,887.68 1852.9,883.5 1852.9,835.5 1857.96,830.44 1882.07,830.44 1887.65,836.02 1887.65,883.23 1883.21,887.68
GND on Top Layer "NONET_L08_P-001" (solid, remove dead copper, pour order 40): 2004.29,899.49 2006.31,897.47 2006.31,780.65 1998.57,772.91 1963.6,772.91 1961.75,774.76 1961.75,899.49
VMAIN_5V0 on Top Layer "NONET_L08_P-001" (solid, remove dead copper, pour order 30): 2615.86,403.96 2624.04,395.78 2646.99,395.78 2651.43,400.22 2659.58,408.36 2659.58,440.38 2666.92,447.72 2700.98,447.72 2700.98,457.53 2623,457.53 2615.86,450.4
GND on Top Layer "NONET_L08_P-001" (solid, remove dead copper, pour order 34): 2600.12,450.4 2550.85,450.4 2550.85,390.56 2591.09,390.56 2600.12,399.58 2600.12,426.78
NetC61_2 on Top Layer "NONET_L08_P-001" (solid, remove dead copper, pour order 24): 2701.04,436.84 2700.02,437.85 2676.22,437.85 2672.95,434.57 2672.95,408.39 2664.47,399.92 2664.47,368.59 2695.97,368.59 2695.97,424.16 2701.04,429.22
BOOST_FSW on Top Layer "NONET_L08_P-001" (solid, remove dead copper, pour order 25): 2799.83,438.59 2772.77,438.59 2770.96,436.78 2770.96,418.71 2779.83,409.85 2800.19,409.85 2811.86,398.18 2811.86,370.04 2813.29,368.61 2846.19,368.61 2846.19,392.23
BOOST_SW on Top Layer "NONET_L08_P-001" (solid, remove dead copper, pour order 23): 2722.81,258.5 2716.74,264.58 2716.74,363.56 2714.68,365.62 2714.68,457.59 2714.81,457.47 2758.68,457.47 2758.68,414.48 2777.45,395.7 2798.94,395.7 2798.94,261.43 2796.05,258.54
VMAIN_5V0 on Top Layer "NONET_L08_P-001" (solid, remove dead copper, pour order 20): 2622.51,131 2634.95,118.56 2634.74,96.58 2641.96,89.35 2692.98,89.35 2698.73,95.1 2698.73,339.02 2692.67,345.07 2642.46,345.07 2635.69,338.31 2635.69,286.7 2605.53,256.54 2559.2,256.54 2541.59,274.15 2413.51,274.15 2404.99,265.63 2404.99,235.13 2432.71,235.13 2476.56,191.27 2491.73,191.27 2507.78,175.22 2507.78,142.01 2518.78,131
GND on Top Layer "NONET_L08_P-001" (solid, remove dead copper, pour order 19): 2460.4,289.39 2417.8,289.39 2397.09,268.67 2397.09,201.89 2393.04,197.84 2359.25,197.84 2357.06,200.03 2357.06,269.34 2349.83,276.56 2303.98,276.56 2295.11,285.42 2295.11,357.66 2311.3,373.84 2449.56,373.84 2460.81,362.58
VMAIN_5V0_IN on Top Layer "NONET_L08_P-001" (solid, remove dead copper, pour order 15): 2231.01,278.79 2231.37,279.15 2231.6,279.16 2291.45,279.16 2291.96,278.65 2291.95,278.17 2291.95,268.25 2294.57,265.63 2295.31,265.63 2349.8,265.63 2349.8,235.11 2316.89,235.11 2303.6,221.82 2232.23,221.82 2231.01,223.04
GND on L04_GND2 "NONET_L08_P-001" (solid, remove dead copper, pour order 93): 0,2500 3110.24,2500 3110.24,0 -0.05,0
GND on L02_GND1 "NONET_L08_P-001" (solid, remove dead copper, pour order 94): 0,2420 80,2500 3110.24,2500 3110.24,0 -0.05,0
GND on L03_SIG1 "GND_L03_P100" (solid, remove dead copper, pour order 100): 0,2500 3110.24,2500 3110.24,0 0,0
GND on L08_SIG2 "GND_L08_P102" (solid, remove dead copper, pour order 102): -3.26,2503.32 3106.98,2503.32 3106.98,3.32 -3.26,3.32
GND on L09_GND4 "GND_L09_P104" (solid, remove dead copper, pour order 104): 0,2500 3110.24,2500 3110.24,0 0,0
GND on L07_GND3 "GND_L07_P106" (solid, remove dead copper, pour order 106): 0,2500 3110.24,2500 3110.24,0 0,0

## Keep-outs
Keep-Out Layer:
  circle w0.5: c2580.5,1107.46 r40
  circle w0.5: c204.88,1899.96 r40
  circle w0.5: c2580.12,1899.96 r40
  circle w0.5: c2580.12,320.04 r40
  circle w0.5: c2184.96,400.12 r40
  circle w0.5: c605.04,400.12 r40
  circle w0.5: c204.88,320.04 r40
  circle w0.5: c410,155 r150
  circle w0.5: c410,2060 r150
  circle w0.5: c2380,2060 r150
  circle w0.5: c2170,590 r128

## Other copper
Top Layer:
  pour cut-out: 1564.39,1121.33 1561.28,1118.22 1775.22,1118.22 1775.22,1156.51 1769.8,1161.92 1565.53,1161.92 1564.39,1163.06
  pour cut-out: 899.4,1454.17 1214.36,1454.17 1214.36,1107.71 899.4,1107.71
  text ".Layer_Name" at 253.97,-2333.76 h60
L02_GND1:
  text ".Layer_Name" at 227.68,-2342.53 h60
L03_SIG1:
  text ".Layer_Name" at 262.73,-2325 h60
L04_GND2:
  text ".Layer_Name" at 332.81,-2325 h60
L07_GND3:
  text ".Layer_Name" at 350.34,-2360.05 h60
L08_SIG2:
  text ".Layer_Name" at 315.29,-2316.24 h60
L09_GND4:
  text ".Layer_Name" at 332.81,-2351.29 h60
L05_PWR1:
  text ".Layer_Name" at 280.25,-2342.53 h60
L06_PWR2:
  text ".Layer_Name" at 315.29,-2351.29 h60
Bottom Layer:
  text ".Layer_Name" at 141.56,-2331.22 h60

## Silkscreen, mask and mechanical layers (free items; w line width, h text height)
Top Overlay:
  region: 1240.63,194.82 778.28,194.82 778.28,136.03 1240.63,136.03
  lines w4: 82.29,1616.18 327.18,1616.18 377,1666 377,1839 320,1896 289,1896 ; 83.36,1616.18 70.82,1616.18 29.49,1657.51 29.49,1895.18 42.32,1908 43,1908 107,1908 148,1867 261,1867 289,1895 ; 399,1093 399,1112.33 405.94,1119.28 405.94,1132.44 ; 1322.94,999.45 1322.94,946.06 1339,930 1445,930 1500,985 1500,1175 1472.75,1202.25 1472.75,1236.97 1392.97,1236.97 1384,1228 1384,1029.32 1354.12,999.45 ; 2917,1341 2930,1354 2930,1369 ; 52,1100 81.03,1070.97 349.97,1070.97 396,1117 396,1258 384,1270 169,1270 121,1318 74,1318 52,1296 52,1100 ; 2172,2219 2185,2206 2261,2206 2292,2237 2292,2411 2281,2422 2186,2422 2172,2408 2172,2219
  lines w5: 688,363 688,432 769.77,513.77 769.77,646.7 782.07,659 908.81,659 917,650.81 917,441 930,428 930,358 921,349 702,349 688,363
  lines w6: 836.48,2146.14 855.14,2146.14 876.35,2167.35 884.51,2167.35 ; 1828.14,2035.56 1850.56,2035.56 1863.46,2048.46 1863.46,2104.42 ; 1863.46,2143.79 1863.46,2195.53 1896.04,2228.11 1898.39,2228.11 ; 1896.54,2208.65 2161.65,2208.65 2172,2219 ; 2172,2170 2220,2170 2233,2183
  lines w10: 774.8,132.81 774.8,197.29 ; 657,132.46 657,198.29 1244.45,198.29 1244.45,132.46 657,132.46
  text "BOOTMODE SWITCH" at 360.39,2435.11 h25
  text "PORz" at 968.44,2429.39 h25
  text "INTn" at 1240.72,2426.61 h25
  text "RESETn" at 1536.52,2423.91 h25
  text "1V8_LDO4" at 2656.85,2254.08 h22
  text "3V3_LDO2" at 2355.56,2191.73 h25
  text "VSYS_3V3_LDO1" at 2908.84,1909.3 h22 r90
  text "A" at 98,1843 h25
  text "VCC_1V2" at 1639.89,1522.9 h25
  text "A" at 253,1229 h25
  text "*" at 1722.08,1123.52 h55
  text "B" at 1463.93,1031.62 h25
  text "5V0_LDO3" at 2530.11,914.48 h25
  text "USERLED0" at 1585.2,739.06 h25 r90
  text "USERLED1" at 1451.3,737.67 h25 r90
  text "VMAIN_5V0" at 2560.99,693.67 h25
  text "B" at 884.23,495.68 h25
  text "PROC195 E1" at 787.13,266.73 h30
  text "FY23-24/02486000101" at 676.18,215.43 h30
  text "SL#" at 679,149 h50
  text ".Layer_Name" at 24,-2370 h60
Bottom Overlay:
  rectangle: 2316.93,2239.43 2779.28,2298.22
  lines w6: 1090,942 1090,944 1100,954 1100,995 ; 1269.37,2126.57 1269.37,2139.73 1279.64,2150 ; 2150.25,2058.47 2166.03,2058.47 2193.56,2086 2219,2086 2231,2098
  lines w10: 2782.76,2236.21 2782.76,2300.69 ; 2313.11,2235.86 2313.11,2301.69 2948.93,2301.69 2948.93,2235.86 2313.11,2235.86
  text "ASSY#" at 2941.77,2251.77 h50
  text ".Layer_Name" at 819,-2374 h60
Top Solder:
  text ".Layer_Name" at 20,-2375 h60
Bottom Solder:
  text ".Layer_Name" at 30,-2377 h60
Drill Guide:
  text ".Layer_Name" at 86.11,-2345.75 h60
M1 Board Outline:
  lines w5: 467.53,-78.74 0,-78.74 0,-354.34 3110.24,-354.34 3110.24,-78.74 2642.71,-78.74 ; 467.53,2578.74 0,2578.74 0,2854.34 3110.24,2854.34 3110.24,2578.74 2642.71,2578.74 ; 738.4,-78.74 1419.53,-78.74 ; 738.4,2578.74 1419.53,2578.74 ; 1690.4,-78.74 2371.84,-78.74 ; 1690.4,2578.74 2371.84,2578.74
  lines w6: 0,0 3110.24,0 3110.24,2500 0,2500 0,0
M2 Board Dimensions:
  text ".Layer_Name" at 32,-2373 h60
